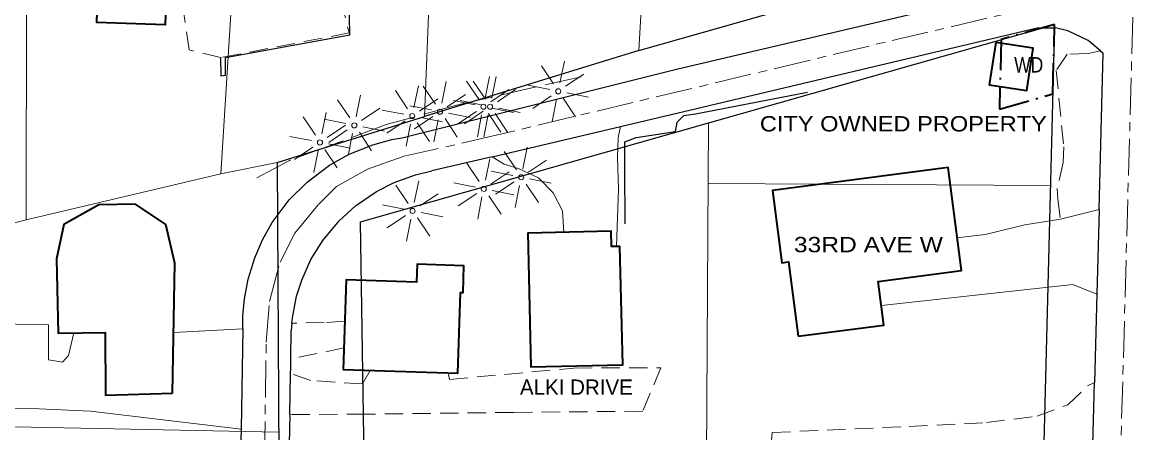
# Model space of a CAD drawing. Extents: x -861682 to -858969, y -1797841 to -1795153.
# Drawn here: x -861428.5 to -860994.8, y -1796923.4 to -1796763 of the extents above; entities that cross this region are included whole.
import ezdxf

# ---------------------------------------------------------------- set-up
doc = ezdxf.new("R2010")
doc.units = 0
doc.header["$LTSCALE"] = 2.4
for name, pattern in [('DOT_DASHED', [7.7, 5, -1.2, 0.3, -1.2]), ('LONG_DASH_SHORT_DASH', [9.9, 6, -1.2, 1.5, -1.2]), ('LONG_DASHED', [7.5, 6, -1.5]), ('MEDIUM_DASHED', [4.5, 3, -1.5])]:
    doc.linetypes.add(name, pattern=pattern)
for name, color, linetype, lineweight in [('10', 7, 'Continuous', 25), ('11', 7, 'Continuous', 13), ('12', 7, 'Continuous', 35), ('14', 7, 'Continuous', 25), ('17', 7, 'Continuous', 13), ('30', 7, 'Continuous', 13), ('32', 7, 'LONG_DASH_SHORT_DASH', 13), ('42', 7, 'Continuous', 25), ('46', 7, 'Continuous', 13), ('48', 7, 'DOT_DASHED', 35), ('52', 7, 'LONG_DASHED', 13)]:
    doc.layers.add(name, color=color, linetype=linetype, lineweight=lineweight)

msp = doc.modelspace()

# ---------------------------------------------------------------- linework, layer by layer
at = {"layer": '10'}
for p, q in [((-861006.642, -1796774.175), (-861005.625, -1796775.013)), ((-861007.253, -1796836.234), (-861005.625, -1796775.013)), ((-861244.622, -1796815.528), (-861194.427, -1796803.667)), ((-861244.622, -1796815.528), (-861268.293, -1796821.122)), ((-861323.035, -1796880.611), (-861323.305, -1796883.452)), ((-861323.437, -1796894.55), (-861323.305, -1796883.452)), ((-861323.862, -1796916.281), (-861323.522, -1796900.214)), ((-861010.143, -1796944.779), (-861009.05, -1796903.728)), ((-861323.862, -1796916.281), (-861324.107, -1796927.841))]:
    msp.add_line(p, q, dxfattribs=at)
for points in [[(-861015.67, -1796744.537), (-861172.1, -1796781.298), (-861278.502, -1796807.938)], [(-861194.427, -1796803.667), (-861031.411, -1796765.147), (-861024.326, -1796765.118)], [(-861006.642, -1796774.175), (-861011.568, -1796770.121), (-861019.479, -1796766.33), (-861024.326, -1796765.118)], [(-861342.201, -1796882.821), (-861342.229, -1796881.127), (-861342.17, -1796877.822), (-861341.581, -1796871.033), (-861340.159, -1796863.455), (-861337.572, -1796855.032), (-861334.496, -1796847.962), (-861330.696, -1796841.253), (-861324.096, -1796832.441), (-861317.089, -1796825.432), (-861308.279, -1796818.83), (-861300.581, -1796814.543), (-861291.38, -1796810.861), (-861283.93, -1796808.874), (-861278.502, -1796807.938)], [(-861323.035, -1796880.611), (-861322.833, -1796878.476), (-861321.171, -1796870.075), (-861319.166, -1796863.777), (-861315.551, -1796855.743), (-861310.918, -1796848.25), (-861304.588, -1796840.626), (-861298.075, -1796834.694), (-861289.894, -1796829.103), (-861283.015, -1796825.621), (-861274.727, -1796822.636), (-861268.293, -1796821.122)], [(-861007.253, -1796836.234), (-861008.134, -1796869.314), (-861009.05, -1796903.728)], [(-861342.201, -1796882.821), (-861342.913, -1796922.043), (-861342.989, -1796926.297)], [(-861323.522, -1796900.214), (-861323.483, -1796898.332), (-861323.437, -1796894.55)]]:
    msp.add_lwpolyline(points, dxfattribs=at)
at = {"layer": '11'}
for p, q in [((-861022.372, -1796839.974), (-861007.253, -1796836.234)), ((-861369.275, -1796884.274), (-861342.201, -1796882.821))]:
    msp.add_line(p, q, dxfattribs=at)
at = {"layer": '11', "linetype": 'MEDIUM_DASHED'}
msp.add_line((-861302.661, -1796890.296), (-861323.437, -1796894.55), dxfattribs=at)
for points in [[(-861303.847, -1796754.316), (-861300.63, -1796767.173), (-861350.894, -1796776.821), (-861363.187, -1796773.801), (-861365.373, -1796758.695), (-861366.4, -1796738.153), (-861365.018, -1796729.41), (-861364.964, -1796684.067), (-861361.24, -1796633.411)], [(-861006.642, -1796774.175), (-861011.533, -1796775.223), (-861019.797, -1796775.492), (-861024.023, -1796781.885), (-861021.07, -1796811.63), (-861021.281, -1796817.771), (-861023.602, -1796827.935), (-861023.349, -1796832.185), (-861022.372, -1796839.974)], [(-861302.322, -1796879.821), (-861310.33, -1796880.331), (-861323.035, -1796880.611)], [(-861261.901, -1796900.066), (-861261.355, -1796902.57), (-861212.723, -1796898.125), (-861178.716, -1796897.988), (-861185.733, -1796915.02), (-861236.27, -1796915.459), (-861294.363, -1796916.164), (-861323.862, -1796916.281)], [(-861292.432, -1796899.064), (-861295.355, -1796904.36), (-861315.671, -1796903.024), (-861323.522, -1796900.214)], [(-861116.694, -1796950.677), (-861120.23, -1796936.01), (-861136.522, -1796937.02), (-861135.16, -1796923.317), (-861081.56, -1796920.977), (-861051.337, -1796919.439), (-861031.509, -1796916.998), (-861019.483, -1796912.462), (-861011.719, -1796905.11), (-861009.05, -1796903.728)]]:
    msp.add_lwpolyline(points, dxfattribs=at)
at = {"layer": '11'}
for points in [[(-861196.074, -1796850.624), (-861195.292, -1796828.151), (-861195.577, -1796815.872), (-861195.372, -1796808.078), (-861194.427, -1796803.667)], [(-861216.683, -1796845.14), (-861217.221, -1796836.741), (-861220.791, -1796829.67), (-861226.483, -1796823.789), (-861234.054, -1796820.277), (-861239.966, -1796818.411), (-861244.622, -1796815.528)], [(-861062.712, -1796847.298), (-861051.868, -1796845.996), (-861036.297, -1796842.155), (-861022.372, -1796839.974)], [(-861092.407, -1796873.654), (-861017.547, -1796865.46), (-861008.134, -1796869.314)], [(-861408.319, -1796884.423), (-861410.412, -1796893.25), (-861412.763, -1796895.857), (-861418.199, -1796894.935), (-861418.254, -1796881.237), (-861443.628, -1796880.735)], [(-861443.61, -1796913.508), (-861421.901, -1796914.079), (-861401.823, -1796914.943), (-861342.913, -1796922.043)]]:
    msp.add_lwpolyline(points, dxfattribs=at)
at = {"layer": '12'}
for points in [[(-861398.516, -1796738.754), (-861371.826, -1796739.591), (-861372.59, -1796763.955), (-861399.28, -1796763.118)], [(-861047.683, -1796770.879), (-861050.214, -1796787.421), (-861035.504, -1796789.672), (-861032.973, -1796773.13)], [(-861124.919, -1796885.726), (-861091.402, -1796881.341), (-861093.629, -1796864.321), (-861061.043, -1796860.057), (-861066.323, -1796819.708), (-861135.026, -1796828.698), (-861131.325, -1796856.985), (-861128.722, -1796856.645)], [(-861369.731, -1796907.963), (-861368.754, -1796857.184), (-861372.357, -1796842.084), (-861384.197, -1796834.102), (-861398.602, -1796834.396), (-861412.269, -1796842.008), (-861415.049, -1796855.48), (-861414.46, -1796884.526), (-861396.041, -1796884.216), (-861395.943, -1796908.777)], [(-861230.623, -1796850.962), (-861229.491, -1796897.717), (-861193.603, -1796896.848), (-861194.723, -1796850.591), (-861198.033, -1796850.671), (-861198.177, -1796844.694), (-861230.755, -1796845.479)], [(-861302.934, -1796898.72), (-861258.057, -1796900.193), (-861257.02, -1796868.604), (-861256.061, -1796868.635), (-861255.722, -1796858.161), (-861274.036, -1796857.568), (-861274.264, -1796864.606), (-861301.8, -1796863.714)]]:
    msp.add_lwpolyline(points, close=True, dxfattribs=at)
at = {"layer": '14'}
for points in [[(-861350.894, -1796776.821), (-861350.866, -1796783.906), (-861348.977, -1796783.662), (-861349.005, -1796776.813), (-861300.407, -1796767.879), (-861300.712, -1796746.627)], [(-861192.639, -1796841.837), (-861192.728, -1796819.639), (-861192.755, -1796812.79), (-861192.768, -1796809.72), (-861188.287, -1796808.049), (-861172.946, -1796805.626), (-861172.252, -1796802.08), (-861169.665, -1796799.472), (-861165.181, -1796798.746), (-861121.288, -1796790.305)]]:
    msp.add_lwpolyline(points, dxfattribs=at)
at = {"layer": '17'}
for p, q in [((-861218.165, -1796786.627), (-861216.439, -1796778.227)), ((-861220.625, -1796787.087), (-861225.415, -1796779.959)), ((-861215.965, -1796788.027), (-861208.869, -1796783.287)), ((-861275.278, -1796796.302), (-861273.552, -1796787.902)), ((-861266.881, -1796795.066), (-861271.671, -1796787.938)), ((-861264.421, -1796794.606), (-861262.695, -1796786.206)), ((-861249.885, -1796793.108), (-861254.675, -1796785.98)), ((-861247.287, -1796793.098), (-861252.077, -1796785.97)), ((-861247.425, -1796792.648), (-861245.699, -1796784.248)), ((-861244.827, -1796792.638), (-861243.101, -1796784.238)), ((-861222.125, -1796789.287), (-861230.587, -1796787.613)), ((-861297.935, -1796799.936), (-861296.209, -1796791.536)), ((-861277.738, -1796796.762), (-861282.528, -1796789.634)), ((-861262.221, -1796796.006), (-861255.125, -1796791.266)), ((-861245.225, -1796794.048), (-861238.129, -1796789.308)), ((-861242.627, -1796794.038), (-861235.531, -1796789.298)), ((-861221.585, -1796791.787), (-861228.811, -1796796.643)), ((-861215.525, -1796790.547), (-861207.045, -1796792.271)), ((-861300.395, -1796800.396), (-861305.185, -1796793.268)), ((-861295.735, -1796801.336), (-861288.639, -1796796.596)), ((-861268.381, -1796797.266), (-861276.843, -1796795.592)), ((-861273.078, -1796797.702), (-861265.982, -1796792.962)), ((-861251.385, -1796795.308), (-861259.847, -1796793.634)), ((-861248.787, -1796795.298), (-861257.249, -1796793.624)), ((-861244.785, -1796796.568), (-861236.305, -1796798.292)), ((-861242.187, -1796796.558), (-861233.707, -1796798.282)), ((-861221.205, -1796801.747), (-861219.525, -1796793.147)), ((-861216.865, -1796792.687), (-861212.065, -1796799.901)), ((-861313.829, -1796807.062), (-861318.619, -1796799.934)), ((-861311.369, -1796806.602), (-861309.643, -1796798.202)), ((-861301.895, -1796802.596), (-861310.357, -1796800.922)), ((-861279.238, -1796798.962), (-861287.7, -1796797.288)), ((-861267.841, -1796799.766), (-861275.067, -1796804.622)), ((-861272.638, -1796800.222), (-861264.158, -1796801.946)), ((-861263.121, -1796800.666), (-861258.321, -1796807.88)), ((-861261.781, -1796798.526), (-861253.301, -1796800.25)), ((-861250.845, -1796797.808), (-861258.071, -1796802.664)), ((-861248.247, -1796797.798), (-861255.473, -1796802.654)), ((-861250.465, -1796807.768), (-861248.785, -1796799.168)), ((-861247.867, -1796807.758), (-861246.187, -1796799.158)), ((-861246.125, -1796798.708), (-861241.325, -1796805.922)), ((-861243.527, -1796798.698), (-861238.727, -1796805.912)), ((-861309.169, -1796808.002), (-861302.073, -1796803.262)), ((-861301.355, -1796805.096), (-861308.581, -1796809.952)), ((-861295.295, -1796803.856), (-861286.815, -1796805.58)), ((-861278.698, -1796801.462), (-861285.924, -1796806.318)), ((-861278.318, -1796811.422), (-861276.638, -1796802.822)), ((-861273.978, -1796802.362), (-861269.178, -1796809.576)), ((-861267.461, -1796809.726), (-861265.781, -1796801.126)), ((-861315.329, -1796809.262), (-861323.791, -1796807.588)), ((-861300.975, -1796815.056), (-861299.295, -1796806.456)), ((-861296.635, -1796805.996), (-861291.835, -1796813.21)), ((-861314.789, -1796811.762), (-861322.015, -1796816.618)), ((-861314.409, -1796821.722), (-861312.729, -1796813.122)), ((-861310.069, -1796812.662), (-861305.269, -1796819.876)), ((-861308.729, -1796810.522), (-861300.249, -1796812.246)), ((-861235.132, -1796820.68), (-861239.922, -1796813.552)), ((-861232.672, -1796820.22), (-861230.946, -1796811.82)), ((-861249.756, -1796825.225), (-861254.546, -1796818.097)), ((-861247.296, -1796824.765), (-861245.57, -1796816.365)), ((-861230.472, -1796821.62), (-861223.376, -1796816.88)), ((-861245.096, -1796826.165), (-861238, -1796821.425)), ((-861236.632, -1796822.88), (-861245.094, -1796821.206)), ((-861277.589, -1796833.839), (-861282.379, -1796826.711)), ((-861275.129, -1796833.379), (-861273.403, -1796824.979)), ((-861251.256, -1796827.425), (-861259.718, -1796825.751)), ((-861236.092, -1796825.38), (-861243.318, -1796830.236)), ((-861235.712, -1796835.34), (-861234.032, -1796826.74)), ((-861231.372, -1796826.28), (-861226.572, -1796833.494)), ((-861230.032, -1796824.14), (-861221.552, -1796825.864)), ((-861272.929, -1796834.779), (-861265.833, -1796830.039)), ((-861250.716, -1796829.925), (-861257.942, -1796834.781)), ((-861250.336, -1796839.885), (-861248.656, -1796831.285)), ((-861245.996, -1796830.825), (-861241.196, -1796838.039)), ((-861244.656, -1796828.685), (-861236.176, -1796830.409)), ((-861279.089, -1796836.039), (-861287.551, -1796834.365)), ((-861278.549, -1796838.539), (-861285.775, -1796843.395)), ((-861278.169, -1796848.499), (-861276.489, -1796839.899)), ((-861273.829, -1796839.439), (-861269.029, -1796846.653)), ((-861272.489, -1796837.299), (-861264.009, -1796839.023))]:
    msp.add_line(p, q, dxfattribs=at)
for centre in [(-861218.825, -1796789.987), (-861248.085, -1796796.008), (-861245.487, -1796795.998), (-861275.938, -1796799.662), (-861265.081, -1796797.966), (-861298.595, -1796803.296), (-861312.029, -1796809.962), (-861233.332, -1796823.58), (-861247.956, -1796828.125), (-861275.789, -1796836.739)]:
    msp.add_circle(centre, 1, dxfattribs=at)
at = {"layer": '30'}
for p, q in [((-861187.233, -1796774.004), (-861180.531, -1796646.914)), ((-861266.2, -1796672.175), (-861271.115, -1796799.834)), ((-861350.814, -1796822.237), (-861342.738, -1796694.237)), ((-861426.818, -1796717.913), (-861427.024, -1796840.227)), ((-861163.628, -1797374.823), (-861160.072, -1796802.305)), ((-861328.727, -1796817.832), (-861350.814, -1796822.237)), ((-861350.814, -1796822.237), (-861427.024, -1796840.227)), ((-861160.219, -1796826.012), (-861026.26, -1796826.737)), ((-861427.024, -1796840.227), (-861492.993, -1796857.056)), ((-861328.164, -1796923.166), (-861466.655, -1796920.485))]:
    msp.add_line(p, q, dxfattribs=at)
at = {"layer": '32'}
for points in [[(-861016.908, -1797697.112), (-861016.908, -1797629.868), (-861015.071, -1797572.938), (-861015.071, -1797447.139), (-861012.317, -1797374.599), (-861007.726, -1797281.857), (-861003.087, -1797084.148), (-860992.207, -1796696.344), (-860992.984, -1796576.661), (-860989.487, -1796449.983), (-860987.933, -1796343.901), (-860987.544, -1796199.737), (-860984.047, -1796080.831), (-860987.933, -1795887.705), (-860991.735, -1795769.455)], [(-861336.345, -1797123.445), (-861333.081, -1796888.015), (-861331.83, -1796872.168), (-861327.659, -1796856.738), (-861321.821, -1796845.478), (-861312.646, -1796834.219), (-861305.557, -1796827.129), (-861293.463, -1796820.457), (-861279.702, -1796815.453), (-861249.874, -1796808.735), (-861088.25, -1796770.144), (-860993.655, -1796747.958)]]:
    msp.add_lwpolyline(points, dxfattribs=at)
at = {"layer": '42'}
for p, q in [((-861187.233, -1796774.004), (-861102.517, -1796749.954)), ((-861187.233, -1796774.004), (-861271.115, -1796799.834)), ((-861328.727, -1796817.832), (-861271.115, -1796799.834)), ((-861328.727, -1796817.832), (-861327.8, -1796991.251))]:
    msp.add_line(p, q, dxfattribs=at)
msp.add_lwpolyline([(-861293.837, -1796992.387), (-861296.182, -1796840.974), (-861024.656, -1796763.832), (-861030.52, -1796993.813)], dxfattribs=at)
at = {"layer": '48'}
msp.add_lwpolyline([(-861045.564, -1796769.772), (-861046.257, -1796796.935), (-861025.349, -1796790.995), (-861024.656, -1796763.832), (-861024.656, -1796763.832)], close=True, dxfattribs=at)
at = {"layer": '52'}
msp.add_lwpolyline([(-861209.874, -1796784.284), (-861257.535, -1796795.102), (-861286.079, -1796803.01), (-861306.595, -1796810.649), (-861324.015, -1796816.96), (-861337.949, -1796824.472)], dxfattribs=at)

# ---------------------------------------------------------------- texts
at = {"layer": '46', "width": 1.2}
msp.add_text('33RD AVE W', height=6, dxfattribs=at).set_placement((-861126.642, -1796852.887))
at = {"layer": '46'}
msp.add_text('ALKI DRIVE', height=6, dxfattribs=at).set_placement((-861233.8, -1796908.603))
at = {"layer": '48'}
for s, width, p in [('WD', 0.85, (-861040.448, -1796782.628)), ('CITY OWNED PROPERTY', 1.15, (-861139.955, -1796805.667))]:
    msp.add_text(s, height=6, dxfattribs=dict(at, width=width)).set_placement(p)

doc.saveas('drawing.dxf')
